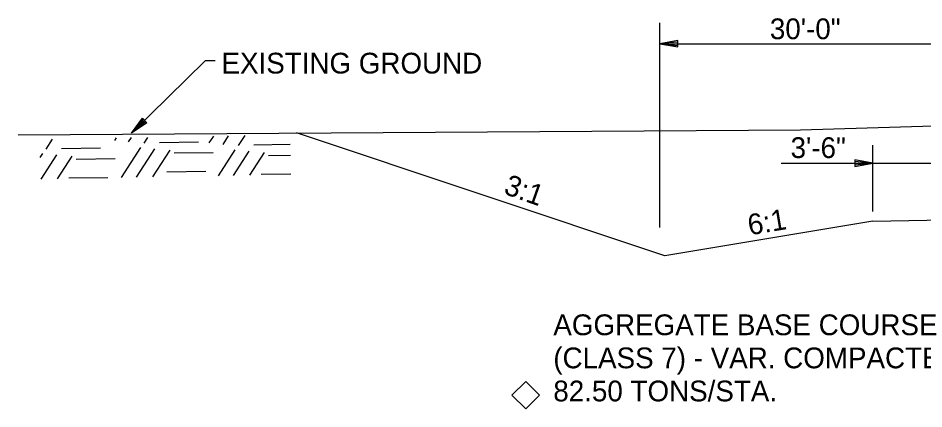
# Model space of a CAD drawing. Extents: x 1734743 to 1735935, y 759845 to 763831.
# Drawn here: x 1735609.8 to 1735662.2, y 760673.1 to 760695.7 of the extents above; entities that cross this region are included whole.
import ezdxf

# ---------------------------------------------------------------- set-up
doc = ezdxf.new("R2010")
doc.units = 0
doc.layers.add('10', color=7, linetype='Continuous')
doc.layers.add('19', color=7, linetype='Continuous')

msp = doc.modelspace()

# ---------------------------------------------------------------- linework, layer by layer
at = {"layer": '10'}
msp.add_lwpolyline([(1735639.162, 760674.708), (1735639.957, 760673.912), (1735639.162, 760673.117), (1735638.366, 760673.912)], close=True, dxfattribs=at)
at = {"layer": '19'}
for p, q in [((1735646.912, 760683.592), (1735646.912, 760695.422)), ((1735647.962, 760694.394), (1735646.912, 760694.21)), ((1735646.912, 760694.21), (1735676.912, 760694.21)), ((1735646.912, 760694.21), (1735647.962, 760694.026)), ((1735647.962, 760694.297), (1735647.192, 760694.236)), ((1735647.192, 760694.184), (1735647.962, 760694.114)), ((1735647.962, 760694.026), (1735647.962, 760694.394)), ((1735616.387, 760689.047), (1735617.009, 760689.914)), ((1735617.009, 760689.914), (1735617.262, 760689.651)), ((1735617.262, 760689.651), (1735616.387, 760689.047)), ((1735616.571, 760689.257), (1735617.07, 760689.844)), ((1735617.201, 760689.712), (1735616.606, 760689.222)), ((1735620.87, 760688.477), (1735621.129, 760688.877)), ((1735621.669, 760688.399), (1735621.988, 760688.893)), ((1735622.56, 760688.323), (1735622.941, 760688.911)), ((1735647.204, 760681.96), (1735625.915, 760689.056)), ((1735611.438, 760688.112), (1735611.819, 760688.7)), ((1735615.415, 760688.614), (1735615.516, 760688.77)), ((1735616.214, 760688.537), (1735616.376, 760688.786)), ((1735617.106, 760688.461), (1735617.328, 760688.804)), ((1735617.995, 760688.515), (1735620.257, 760688.539)), ((1735623.449, 760688.377), (1735625.555, 760688.4)), ((1735659.228, 760684.529), (1735659.228, 760688.361)), ((1735611.107, 760687.635), (1735611.257, 760687.867)), ((1735612.327, 760688.166), (1735614.589, 760688.191)), ((1735615.801, 760686.481), (1735616.925, 760688.216)), ((1735616.661, 760686.497), (1735617.724, 760688.139)), ((1735617.613, 760686.515), (1735618.615, 760688.063)), ((1735618.841, 760687.9), (1735621.103, 760687.925)), ((1735621.414, 760686.587), (1735622.379, 760688.079)), ((1735622.274, 760686.604), (1735623.178, 760688.001)), ((1735623.226, 760686.622), (1735624.07, 760687.925)), ((1735611.152, 760686.392), (1735612.056, 760687.79)), ((1735612.104, 760686.411), (1735612.948, 760687.714)), ((1735613.173, 760687.551), (1735615.435, 760687.576)), ((1735624.295, 760687.763), (1735625.567, 760687.776)), ((1735653.918, 760687.311), (1735664.439, 760687.311)), ((1735658.178, 760687.495), (1735658.178, 760687.128)), ((1735659.228, 760687.311), (1735658.178, 760687.495)), ((1735658.948, 760687.338), (1735658.178, 760687.399)), ((1735658.178, 760687.128), (1735659.228, 760687.311)), ((1735658.178, 760687.215), (1735658.948, 760687.285)), ((1735618.417, 760686.816), (1735620.678, 760686.841)), ((1735612.749, 760686.467), (1735615.011, 760686.492)), ((1735623.871, 760686.679), (1735625.587, 760686.697)), ((1735659.228, 760683.964), (1735674.938, 760684.278)), ((1735659.228, 760683.964), (1735647.204, 760681.96))]:
    msp.add_line(p, q, dxfattribs=at)
for points in [[(1735621.212, 760693.224), (1735620.643, 760693.224), (1735616.387, 760689.047)], [(1735609.825, 760688.951), (1735655.044, 760689.247), (1735666.593, 760689.587), (1735670.546, 760689.084), (1735676.027, 760689.145), (1735685.968, 760689.54), (1735692.6, 760689.5), (1735701.593, 760689.622), (1735708.711, 760689.927)]]:
    msp.add_lwpolyline(points, dxfattribs=at)

# ---------------------------------------------------------------- texts
for s, p in [('30\'-0"', (1735653.273, 760694.473)), ('EXISTING GROUND', (1735621.58, 760692.49)), ('3\'-6"', (1735654.469, 760687.608))]:
    msp.add_text(s, height=1.2, dxfattribs=at).set_placement(p)
for s, rotation, p in [('3:1', 340.4943, (1735637.831, 760685.562)), ('6:1', 9.4511, (1735652.097, 760683.141)), ('AGGREGATE BASE COURSE', 360, (1735640.757, 760677.374)), ('(CLASS 7) - VAR. COMPACTED DEPTH', 360, (1735640.757, 760675.462)), ('82.50 TONS/STA.', 360, (1735640.757, 760673.55))]:
    msp.add_text(s, height=1.2, rotation=rotation, dxfattribs=at).set_placement(p)

doc.saveas('drawing.dxf')
